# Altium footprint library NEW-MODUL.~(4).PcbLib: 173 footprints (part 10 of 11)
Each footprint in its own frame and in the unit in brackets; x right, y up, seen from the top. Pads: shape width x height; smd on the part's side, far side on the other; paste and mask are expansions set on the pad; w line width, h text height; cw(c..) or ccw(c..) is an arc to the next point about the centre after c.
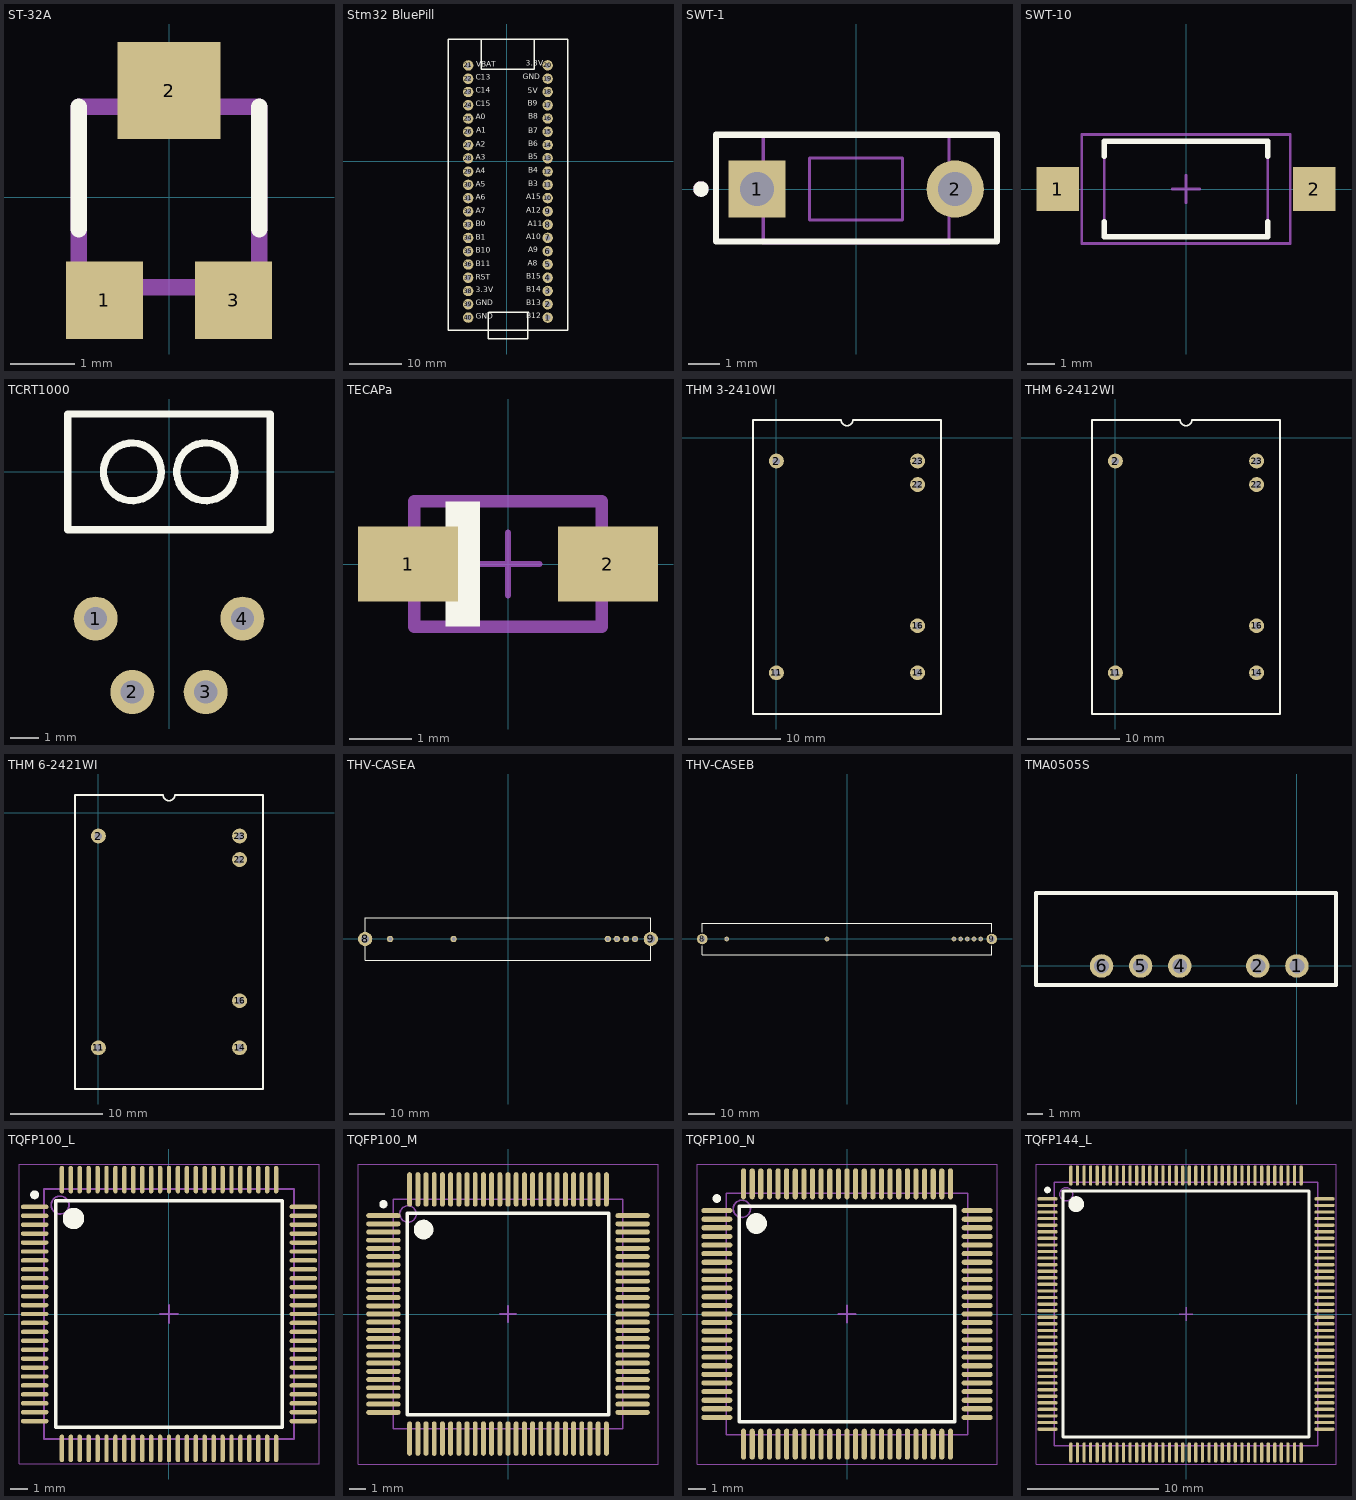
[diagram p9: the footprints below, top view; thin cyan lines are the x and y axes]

## ST-32A [mm]
height 2
pads (3):
  rect 1.2x1.2 smd: 1(-1,-1.6) 3(1,-1.6)
  rect 1.6x1.5 smd: 2(0,1.65)
Top Overlay:
  lines w0.254: -1.4,-0.5 -1.4,1.4 ; 1.4,-0.5 1.4,1.4
Mechanical 1:
  lines w0.254: -1.4,-1.4 -1.4,1.4 1.4,1.4 1.4,-1.4 -1.4,-1.4
3D body "SW3dPS-TRIMMER_PVG3A.STEP": height 2, standoff 0, extent -1.7,-1.7 1.7,1.9

## Stm32 BluePill [mm]
pads (40):
  round 2 hole 1: 1(7.828,-29.909) 2(7.828,-27.343) 3(7.828,-24.803) 4(7.828,-22.263) 5(7.828,-19.723) 6(7.828,-17.183) 7(7.828,-14.643) 8(7.828,-12.103) 9(7.828,-9.563) 10(7.828,-7.023) 11(7.828,-4.483) 12(7.828,-1.943) 13(7.828,0.597) 14(7.828,3.137) 15(7.828,5.677) 16(7.828,8.217) 17(7.828,10.757) 18(7.828,13.297) 19(7.828,15.837) 20(7.828,18.377) 21(-7.386,18.366) 22(-7.386,15.826) 23(-7.386,13.286) 24(-7.386,10.746) 25(-7.386,8.206) 26(-7.386,5.666) 27(-7.386,3.126) 28(-7.386,0.586) 29(-7.386,-1.954) 30(-7.386,-4.494) 31(-7.386,-7.034) 32(-7.386,-9.574) 33(-7.386,-12.114) 34(-7.386,-14.654) 35(-7.386,-17.194) 36(-7.386,-19.734) 37(-7.386,-22.274) 38(-7.386,-24.814) 39(-7.386,-27.354) 40(-7.386,-29.894)
Top Overlay:
  lines w0.254: -11.171,-32.296 11.694,-32.344 ; -11.158,-32.309 -11.222,23.431 11.638,23.431 11.689,-32.309 ; -3.576,-28.918 -3.576,-33.998 4.044,-33.998 4.044,-28.918 ; -3.556,-28.918 -3.556,-33.998 1.778,-33.998 ; -3.449,-28.918 4.171,-28.918 ; -3.429,-28.918 1.905,-28.918 ; 5.288,23.368 5.288,17.653 -4.872,17.653 ; -4.872,17.653 -4.872,23.368 -4.872,17.653
  text "B12" at 3.749,-30.455 h1.78
  text "GND" at -5.913,-30.512 h1.78
  text "B13" at 3.739,-27.946 h1.78
  text "GND" at -5.913,-27.947 h1.78
  text "A1" at -5.842,5.08 h1.78
  text "A0" at -5.913,7.639 h1.78
  text "C14" at -5.913,12.769 h1.78
  text "C13" at -5.913,15.26 h1.78
  text "C15" at -5.913,10.204 h1.78
  text "B6" at 4.15,2.559 h1.78
  text "B4" at 4.087,-2.591 h1.78
  text "B7" at 4.12,5.029 h1.78
  text "B14" at 3.719,-25.375 h1.78
  text "B5" at 4.12,-0.007 h1.78
  text "VBAT" at -5.841,17.78 h1.78
  text "A10" at 3.686,-15.272 h1.78
  text "A12" at 3.686,-10.185 h1.78
  text "A15" at 3.686,-7.601 h1.78
  text "A9" at 4.087,-17.761 h1.78
  text "B3" at 4.12,-5.111 h1.78
  text "A11" at 3.973,-12.751 h1.78
  text "A8" at 4.056,-20.327 h1.78
  text "B15" at 3.749,-22.892 h1.78
  text "3.3V" at -5.913,-25.456 h1.78
  text "B1" at -5.913,-15.392 h1.78
  text "B0" at -5.913,-12.834 h1.78
  text "A7" at -5.913,-10.287 h1.78
  text "A6" at -5.913,-7.703 h1.78
  text "B11" at -5.913,-20.447 h1.78
  text "B10" at -5.913,-17.863 h1.78
  text "RST" at -5.913,-22.994 h1.78
  text "A4" at -5.913,-2.692 h1.78
  text "A3" at -5.913,-0.107 h1.78
  text "A2" at -5.913,2.438 h1.78
  text "A5" at -5.913,-5.214 h1.78
  text "GND" at 3.048,15.386 h1.78
  text "3.3V" at 3.612,17.901 h1.78
  text "B8" at 4.12,7.74 h1.78
  text "B9" at 3.993,10.28 h1.78
  text "5V" at 3.993,12.693 h1.78
3D body "STM32.step": height 12.31, standoff -5.96, extent -11.176,-33.274 11.684,24.286

## SWT-1 [mm] "Switch, 2 Pin"
pads (2):
  rect 1.85x1.85 hole 1.1 mask+0.1: 1(-3.2,0)
  round 1.85 hole 1.1 mask+0.1: 2(3.2,0)
Top Overlay:
  circle w0.25: c-5.011,-0.001 r0.125
  lines w0.2: -4.53,-1.7 4.55,-1.7 4.55,1.75 -4.53,1.75 -4.53,-1.7
Mechanical 1:
  circle w0.25: c-5.015,0 r0.125
  lines w0.1: -3,-0.5 -3.25,-0.5 -3.25,0.5 -3,0.5 ; 3,-0.5 3.25,-0.5 3.25,0.5 3,0.5 ; -3,-1.75 3,-1.75 3,1.75 -3,1.75 -3,-1.75 ; -1.5,-1 -1.5,1 1.5,1 1.5,-1 -1.5,-1
3D body: height 3.5, standoff 0, extent -3,-1.75 3,1.75
3D body: height 3.6, standoff 3.5, extent -3,-1.75 3,1.75
3D body: height 4.3, standoff 3.5, extent -1.5,-1 1.5,1
3D body: height 1.75, standoff -3.3, extent -3.25,-0.5 -3,0.5
3D body: height 1.75, standoff -3.3, extent 3,-0.5 3.25,0.5

## SWT-10 [mm] "2-Leads, Body 6,0x3,5mm, IPC Medium Density"
height 4
pads (2):
  rect 1.556x1.6 smd: 1(-4.7,0) 2(4.7,0)
Top Overlay:
  lines w0.2: -3,-1.2 -3,-1.75 3,-1.75 3,-1.2 ; -3,1.2 -3,1.75 3,1.75 3,1.2
Mechanical 13:
  lines w0.1: -3,-1.75 3,-1.75 3,1.75 -3,1.75 -3,-1.75
Mechanical 15:
  lines w0.1: -0.5,0 0.5,0 ; 0,-0.5 0,0.5 ; -3.825,-2 3.825,-2 3.825,2 -3.825,2 -3.825,-2
3D body "User Library-SWT-10.step": height 4.3, standoff 0, extent -5.1,-1.8 5.1,1.7

## TCRT1000 [mil]
height 98.43
pads (4):
  round 60 hole 31.5: 1(-100,-200) 2(-50,-300) 3(50,-300) 4(100,-200)
Top Overlay:
  circle w10: c50,0 r39.37
  circle w10: c-50,0 r39.37
  lines w10: -137.8,-78.74 -68.9,-78.74 -34.45,-78.74 34.45,-78.74 68.9,-78.74 137.8,-78.74 137.8,78.74 -137.8,78.74 -137.8,-78.74

## TECAPa [mm]
pads (2):
  rect 1.6x1.2 smd: 1(-1.6,0) 2(1.6,0)
Top Overlay:
  rectangle: -1,-1 -0.45,1
Mechanical 15:
  lines w0.1: -0.5,0 0.5,0 ; 0,-0.5 0,0.5
  lines w0.2: -1.5,-1 1.5,-1 1.5,1 -1.5,1 -1.5,-1

## THM 3-2410WI [mm]
pads (6):
  round 1.6 / inner oval 1.8x1.6 / far side round 1.6 hole 0.8: 2(0,-2.54) 11(0,-25.4) 14(15.24,-25.4) 16(15.24,-20.32) 22(15.24,-5.08) 23(15.24,-2.54)
Top Overlay:
  lines w0.2: -2.54,-29.845 -2.54,1.905 6.985,1.905 ccw(c7.62,1.905) 8.255,1.905 17.78,1.905 17.78,-29.845 -2.54,-29.845
3D body "User Library-TracoPSU-Ten5-2423.step": height 10.06, standoff -2, extent -2.4,-30 17.6,2

## THM 6-2412WI [mm]
pads (6):
  round 1.6 / inner oval 1.8x1.6 / far side round 1.6 hole 0.8: 2(0,-2.54) 11(0,-25.4) 14(15.24,-25.4) 16(15.24,-20.32) 22(15.24,-5.08) 23(15.24,-2.54)
Top Overlay:
  lines w0.2: -2.54,-29.845 -2.54,1.905 6.985,1.905 ccw(c7.62,1.905) 8.255,1.905 17.78,1.905 17.78,-29.845 -2.54,-29.845
3D body "User Library-TracoPSU-Ten5-2423.step": height 10.06, standoff -2, extent -2.4,-30 17.6,2

## THM 6-2421WI [mm]
pads (6):
  round 1.6 / inner oval 1.8x1.6 / far side round 1.6 hole 0.8: 2(0,-2.54) 11(0,-25.4) 14(15.24,-25.4) 16(15.24,-20.32) 22(15.24,-5.08) 23(15.24,-2.54)
Top Overlay:
  lines w0.2: -2.54,-29.845 17.78,-29.845 17.78,1.905 8.255,1.905 cw(c7.62,1.905) 6.985,1.905 -2.54,1.905 -2.54,-29.845
3D body "User Library-TracoPSU-Ten5-2423.step": height 10.06, standoff -2, extent -2.4,-30 17.6,2

## THV-CASEA [mm]
pads (8):
  round 1.8 hole 1: 1(35.56,0) 2(33.02,0) 3(30.48,0) 4(27.94,0) 5(-15.24,0) 6(-33.02,0)
  round 4 hole 2.2: 8(-40,0) 9(40,0)
Top Overlay:
  lines w0.254: -40,-6 -18,-6 40,-6 40,6 -40,6 -40,-6

## THV-CASEB [mm]
pads (9):
  round 1.8 hole 1: 1(50.8,0) 2(48.26,0) 3(45.72,0) 4(43.18,0) 5(40.64,0) 6(-7.62,0) 7(-45.72,0)
  round 4 hole 2.2: 8(-55,0) 9(55,0)
Top Overlay:
  lines w0.254: -55,-2.5 -55,-6 -18,-6 55,-6 55,-2.5 ; -55,2.5 -55,6 55,6 55,2.5

## TMA0505S [mil]
pads (5):
  round 60 hole 38: 1(0,0) 2(-100,0) 4(-300,0) 5(-400,0) 6(-500,0)
Top Overlay:
  lines w10: -667.72,-49.21 -667.72,187.01 100,187.01 100,-49.21 -667.72,-49.21
3D body "User Library-Traco TMA 0505S.step": height 401.57, standoff -125.98, extent -679.14,-57.09 88.58,183.86

## TQFP100_L [mm] "Thin QFP, 100-Leads, Body 14x14mm, Pitch 0.5mm, IPC High Density"
height 1.2
pads (100):
  oval 1.55x0.25 smd: 1(-7.525,6) 2(-7.525,5.5) 3(-7.525,5) 4(-7.525,4.5) 5(-7.525,4) 6(-7.525,3.5) 7(-7.525,3) 8(-7.525,2.5) 9(-7.525,2) 10(-7.525,1.5) 11(-7.525,1) 12(-7.525,0.5) 13(-7.525,0) 14(-7.525,-0.5) 15(-7.525,-1) 16(-7.525,-1.5) 17(-7.525,-2) 18(-7.525,-2.5) 19(-7.525,-3) 20(-7.525,-3.5) 21(-7.525,-4) 22(-7.525,-4.5) 23(-7.525,-5) 24(-7.525,-5.5) 25(-7.525,-6) 51(7.525,-6) 52(7.525,-5.5) 53(7.525,-5) 54(7.525,-4.5) 55(7.525,-4) 56(7.525,-3.5) 57(7.525,-3) 58(7.525,-2.5) 59(7.525,-2) 60(7.525,-1.5) 61(7.525,-1) 62(7.525,-0.5) 63(7.525,0) 64(7.525,0.5) 65(7.525,1) 66(7.525,1.5) 67(7.525,2) 68(7.525,2.5) 69(7.525,3) 70(7.525,3.5) 71(7.525,4) 72(7.525,4.5) 73(7.525,5) 74(7.525,5.5) 75(7.525,6)
  oval 0.25x1.55 smd: 26(-6,-7.525) 27(-5.5,-7.525) 28(-5,-7.525) 29(-4.5,-7.525) 30(-4,-7.525) 31(-3.5,-7.525) 32(-3,-7.525) 33(-2.5,-7.525) 34(-2,-7.525) 35(-1.5,-7.525) 36(-1,-7.525) 37(-0.5,-7.525) 38(0,-7.525) 39(0.5,-7.525) 40(1,-7.525) 41(1.5,-7.525) 42(2,-7.525) 43(2.5,-7.525) 44(3,-7.525) 45(3.5,-7.525) 46(4,-7.525) 47(4.5,-7.525) 48(5,-7.525) 49(5.5,-7.525) 50(6,-7.525) 76(6,7.525) 77(5.5,7.525) 78(5,7.525) 79(4.5,7.525) 80(4,7.525) 81(3.5,7.525) 82(3,7.525) 83(2.5,7.525) 84(2,7.525) 85(1.5,7.525) 86(1,7.525) 87(0.5,7.525) 88(0,7.525) 89(-0.5,7.525) 90(-1,7.525) 91(-1.5,7.525) 92(-2,7.525) 93(-2.5,7.525) 94(-3,7.525) 95(-3.5,7.525) 96(-4,7.525) 97(-4.5,7.525) 98(-5,7.525) 99(-5.5,7.525) 100(-6,7.525)
Top Overlay:
  circle w0.25: c-7.525,6.675 r0.125
  circle w0.6: c-5.35,5.35 r0.3
  lines w0.2: -6.35,-6.35 -6.35,6.35 6.35,6.35 6.35,-6.35 -6.35,-6.35
Mechanical 13:
  circle w0.1: c-6.1,6.1 r0.5
  lines w0.1: -7,-7 -7,7 7,7 7,-7 -7,-7
Mechanical 15:
  lines w0.05: -8.4,-8.4 -8.4,8.4 8.4,8.4 8.4,-8.4 -8.4,-8.4
  lines w0.1: -0.5,0 0.5,0 ; 0,-0.5 0,0.5
3D body: height 1.2, standoff 0, extent -7,-7 7,7

## TQFP100_M [mm] "Thin QFP, 100-Leads, Body 14x14mm, Pitch 0.5mm, IPC Low Density"
height 1.2
pads (100):
  oval 2.1x0.3 smd: 1(-7.6,6) 2(-7.6,5.5) 3(-7.6,5) 4(-7.6,4.5) 5(-7.6,4) 6(-7.6,3.5) 7(-7.6,3) 8(-7.6,2.5) 9(-7.6,2) 10(-7.6,1.5) 11(-7.6,1) 12(-7.6,0.5) 13(-7.6,0) 14(-7.6,-0.5) 15(-7.6,-1) 16(-7.6,-1.5) 17(-7.6,-2) 18(-7.6,-2.5) 19(-7.6,-3) 20(-7.6,-3.5) 21(-7.6,-4) 22(-7.6,-4.5) 23(-7.6,-5) 24(-7.6,-5.5) 25(-7.6,-6) 51(7.6,-6) 52(7.6,-5.5) 53(7.6,-5) 54(7.6,-4.5) 55(7.6,-4) 56(7.6,-3.5) 57(7.6,-3) 58(7.6,-2.5) 59(7.6,-2) 60(7.6,-1.5) 61(7.6,-1) 62(7.6,-0.5) 63(7.6,0) 64(7.6,0.5) 65(7.6,1) 66(7.6,1.5) 67(7.6,2) 68(7.6,2.5) 69(7.6,3) 70(7.6,3.5) 71(7.6,4) 72(7.6,4.5) 73(7.6,5) 74(7.6,5.5) 75(7.6,6)
  oval 0.3x2.1 smd: 26(-6,-7.6) 27(-5.5,-7.6) 28(-5,-7.6) 29(-4.5,-7.6) 30(-4,-7.6) 31(-3.5,-7.6) 32(-3,-7.6) 33(-2.5,-7.6) 34(-2,-7.6) 35(-1.5,-7.6) 36(-1,-7.6) 37(-0.5,-7.6) 38(0,-7.6) 39(0.5,-7.6) 40(1,-7.6) 41(1.5,-7.6) 42(2,-7.6) 43(2.5,-7.6) 44(3,-7.6) 45(3.5,-7.6) 46(4,-7.6) 47(4.5,-7.6) 48(5,-7.6) 49(5.5,-7.6) 50(6,-7.6) 76(6,7.6) 77(5.5,7.6) 78(5,7.6) 79(4.5,7.6) 80(4,7.6) 81(3.5,7.6) 82(3,7.6) 83(2.5,7.6) 84(2,7.6) 85(1.5,7.6) 86(1,7.6) 87(0.5,7.6) 88(0,7.6) 89(-0.5,7.6) 90(-1,7.6) 91(-1.5,7.6) 92(-2,7.6) 93(-2.5,7.6) 94(-3,7.6) 95(-3.5,7.6) 96(-4,7.6) 97(-4.5,7.6) 98(-5,7.6) 99(-5.5,7.6) 100(-6,7.6)
Top Overlay:
  circle w0.25: c-7.6,6.7 r0.125
  circle w0.6: c-5.15,5.15 r0.3
  lines w0.2: -6.15,-6.15 -6.15,6.15 6.15,6.15 6.15,-6.15 -6.15,-6.15
Mechanical 13:
  circle w0.1: c-6.1,6.1 r0.5
  lines w0.1: -7,-7 -7,7 7,7 7,-7 -7,-7
Mechanical 15:
  lines w0.05: -9.15,-9.15 -9.15,9.15 9.15,9.15 9.15,-9.15 -9.15,-9.15
  lines w0.1: -0.5,0 0.5,0 ; 0,-0.5 0,0.5
3D body: height 1.2, standoff 0, extent -7,-7 7,7

## TQFP100_N [mm] "Thin QFP, 100-Leads, Body 14x14mm, Pitch 0.5mm, IPC Medium Density"
height 1.2
pads (100):
  oval 1.8x0.3 smd: 1(-7.55,6) 2(-7.55,5.5) 3(-7.55,5) 4(-7.55,4.5) 5(-7.55,4) 6(-7.55,3.5) 7(-7.55,3) 8(-7.55,2.5) 9(-7.55,2) 10(-7.55,1.5) 11(-7.55,1) 12(-7.55,0.5) 13(-7.55,0) 14(-7.55,-0.5) 15(-7.55,-1) 16(-7.55,-1.5) 17(-7.55,-2) 18(-7.55,-2.5) 19(-7.55,-3) 20(-7.55,-3.5) 21(-7.55,-4) 22(-7.55,-4.5) 23(-7.55,-5) 24(-7.55,-5.5) 25(-7.55,-6) 51(7.55,-6) 52(7.55,-5.5) 53(7.55,-5) 54(7.55,-4.5) 55(7.55,-4) 56(7.55,-3.5) 57(7.55,-3) 58(7.55,-2.5) 59(7.55,-2) 60(7.55,-1.5) 61(7.55,-1) 62(7.55,-0.5) 63(7.55,0) 64(7.55,0.5) 65(7.55,1) 66(7.55,1.5) 67(7.55,2) 68(7.55,2.5) 69(7.55,3) 70(7.55,3.5) 71(7.55,4) 72(7.55,4.5) 73(7.55,5) 74(7.55,5.5) 75(7.55,6)
  oval 0.3x1.8 smd: 26(-6,-7.55) 27(-5.5,-7.55) 28(-5,-7.55) 29(-4.5,-7.55) 30(-4,-7.55) 31(-3.5,-7.55) 32(-3,-7.55) 33(-2.5,-7.55) 34(-2,-7.55) 35(-1.5,-7.55) 36(-1,-7.55) 37(-0.5,-7.55) 38(0,-7.55) 39(0.5,-7.55) 40(1,-7.55) 41(1.5,-7.55) 42(2,-7.55) 43(2.5,-7.55) 44(3,-7.55) 45(3.5,-7.55) 46(4,-7.55) 47(4.5,-7.55) 48(5,-7.55) 49(5.5,-7.55) 50(6,-7.55) 76(6,7.55) 77(5.5,7.55) 78(5,7.55) 79(4.5,7.55) 80(4,7.55) 81(3.5,7.55) 82(3,7.55) 83(2.5,7.55) 84(2,7.55) 85(1.5,7.55) 86(1,7.55) 87(0.5,7.55) 88(0,7.55) 89(-0.5,7.55) 90(-1,7.55) 91(-1.5,7.55) 92(-2,7.55) 93(-2.5,7.55) 94(-3,7.55) 95(-3.5,7.55) 96(-4,7.55) 97(-4.5,7.55) 98(-5,7.55) 99(-5.5,7.55) 100(-6,7.55)
Top Overlay:
  circle w0.25: c-7.55,6.7 r0.125
  circle w0.6: c-5.25,5.25 r0.3
  lines w0.2: -6.25,-6.25 -6.25,6.25 6.25,6.25 6.25,-6.25 -6.25,-6.25
Mechanical 13:
  circle w0.1: c-6.1,6.1 r0.5
  lines w0.1: -7,-7 -7,7 7,7 7,-7 -7,-7
Mechanical 15:
  lines w0.05: -8.7,-8.7 -8.7,8.7 8.7,8.7 8.7,-8.7 -8.7,-8.7
  lines w0.1: -0.5,0 0.5,0 ; 0,-0.5 0,0.5
3D body "SW3dPS-TQFP100-1.STEP": height 1.6, standoff -0.02, extent -8,-8 8,8

## TQFP144_L [mm] "Thin QFP, 144-Leads, Body 20x20mm, Pitch 0.5mm, IPC High Density"
height 1.6
pads (144):
  oval 1.55x0.25 smd: 1(-10.525,8.75) 2(-10.525,8.25) 3(-10.525,7.75) 4(-10.525,7.25) 5(-10.525,6.75) 6(-10.525,6.25) 7(-10.525,5.75) 8(-10.525,5.25) 9(-10.525,4.75) 10(-10.525,4.25) 11(-10.525,3.75) 12(-10.525,3.25) 13(-10.525,2.75) 14(-10.525,2.25) 15(-10.525,1.75) 16(-10.525,1.25) 17(-10.525,0.75) 18(-10.525,0.25) 19(-10.525,-0.25) 20(-10.525,-0.75) 21(-10.525,-1.25) 22(-10.525,-1.75) 23(-10.525,-2.25) 24(-10.525,-2.75) 25(-10.525,-3.25) 26(-10.525,-3.75) 27(-10.525,-4.25) 28(-10.525,-4.75) 29(-10.525,-5.25) 30(-10.525,-5.75) 31(-10.525,-6.25) 32(-10.525,-6.75) 33(-10.525,-7.25) 34(-10.525,-7.75) 35(-10.525,-8.25) 36(-10.525,-8.75) 73(10.525,-8.75) 74(10.525,-8.25) 75(10.525,-7.75) 76(10.525,-7.25) 77(10.525,-6.75) 78(10.525,-6.25) 79(10.525,-5.75) 80(10.525,-5.25) 81(10.525,-4.75) 82(10.525,-4.25) 83(10.525,-3.75) 84(10.525,-3.25) 85(10.525,-2.75) 86(10.525,-2.25) 87(10.525,-1.75) 88(10.525,-1.25) 89(10.525,-0.75) 90(10.525,-0.25) 91(10.525,0.25) 92(10.525,0.75) 93(10.525,1.25) 94(10.525,1.75) 95(10.525,2.25) 96(10.525,2.75) 97(10.525,3.25) 98(10.525,3.75) 99(10.525,4.25) 100(10.525,4.75) 101(10.525,5.25) 102(10.525,5.75) 103(10.525,6.25) 104(10.525,6.75) 105(10.525,7.25) 106(10.525,7.75) 107(10.525,8.25) 108(10.525,8.75)
  oval 0.25x1.55 smd: 37(-8.75,-10.525) 38(-8.25,-10.525) 39(-7.75,-10.525) 40(-7.25,-10.525) 41(-6.75,-10.525) 42(-6.25,-10.525) 43(-5.75,-10.525) 44(-5.25,-10.525) 45(-4.75,-10.525) 46(-4.25,-10.525) 47(-3.75,-10.525) 48(-3.25,-10.525) 49(-2.75,-10.525) 50(-2.25,-10.525) 51(-1.75,-10.525) 52(-1.25,-10.525) 53(-0.75,-10.525) 54(-0.25,-10.525) 55(0.25,-10.525) 56(0.75,-10.525) 57(1.25,-10.525) 58(1.75,-10.525) 59(2.25,-10.525) 60(2.75,-10.525) 61(3.25,-10.525) 62(3.75,-10.525) 63(4.25,-10.525) 64(4.75,-10.525) 65(5.25,-10.525) 66(5.75,-10.525) 67(6.25,-10.525) 68(6.75,-10.525) 69(7.25,-10.525) 70(7.75,-10.525) 71(8.25,-10.525) 72(8.75,-10.525) 109(8.75,10.525) 110(8.25,10.525) 111(7.75,10.525) 112(7.25,10.525) 113(6.75,10.525) 114(6.25,10.525) 115(5.75,10.525) 116(5.25,10.525) 117(4.75,10.525) 118(4.25,10.525) 119(3.75,10.525) 120(3.25,10.525) 121(2.75,10.525) 122(2.25,10.525) 123(1.75,10.525) 124(1.25,10.525) 125(0.75,10.525) 126(0.25,10.525) 127(-0.25,10.525) 128(-0.75,10.525) 129(-1.25,10.525) 130(-1.75,10.525) 131(-2.25,10.525) 132(-2.75,10.525) 133(-3.25,10.525) 134(-3.75,10.525) 135(-4.25,10.525) 136(-4.75,10.525) 137(-5.25,10.525) 138(-5.75,10.525) 139(-6.25,10.525) 140(-6.75,10.525) 141(-7.25,10.525) 142(-7.75,10.525) 143(-8.25,10.525) 144(-8.75,10.525)
Top Overlay:
  circle w0.25: c-10.525,9.425 r0.125
  circle w0.6: c-8.35,8.35 r0.3
  lines w0.2: -9.35,-9.35 -9.35,9.35 9.35,9.35 9.35,-9.35 -9.35,-9.35
Mechanical 13:
  circle w0.1: c-9.1,9.1 r0.5
  lines w0.1: -10,-10 -10,10 10,10 10,-10 -10,-10
Mechanical 15:
  lines w0.05: -11.4,-11.4 -11.4,11.4 11.4,11.4 11.4,-11.4 -11.4,-11.4
  lines w0.1: -0.5,0 0.5,0 ; 0,-0.5 0,0.5
3D body: height 1.6, standoff 0, extent -10,-10 10,10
